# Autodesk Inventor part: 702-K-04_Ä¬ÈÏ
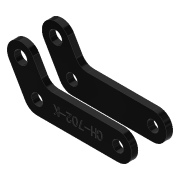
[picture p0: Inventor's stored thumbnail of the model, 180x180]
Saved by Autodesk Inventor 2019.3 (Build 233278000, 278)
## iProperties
Created: 2010-06
Part Number: 702-K-04_Ä¬ÈÏ
Material: Ogólny
Document SubType Name: Modeling
Designer: CADENGINEERING4
Density: 1 g/cm^3
Appearance: Gładki — czarny
Author: CADENGINEERING4
Revision Number: ÈÎºÎ
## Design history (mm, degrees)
feature "NONE"
feature "NONE:1"
node "Bryła1"
node "Bryła2"
